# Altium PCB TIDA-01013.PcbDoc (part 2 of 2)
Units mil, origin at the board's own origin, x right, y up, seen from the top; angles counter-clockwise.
Board outline 2500 x 2300 mil, 4 copper layers (Top Layer, Layer 2 -GND, Layer 3 - PWR, Bottom Layer), stack 59.034 mil thick; 218 components, 101 nets, 532 pads, 275 vias.
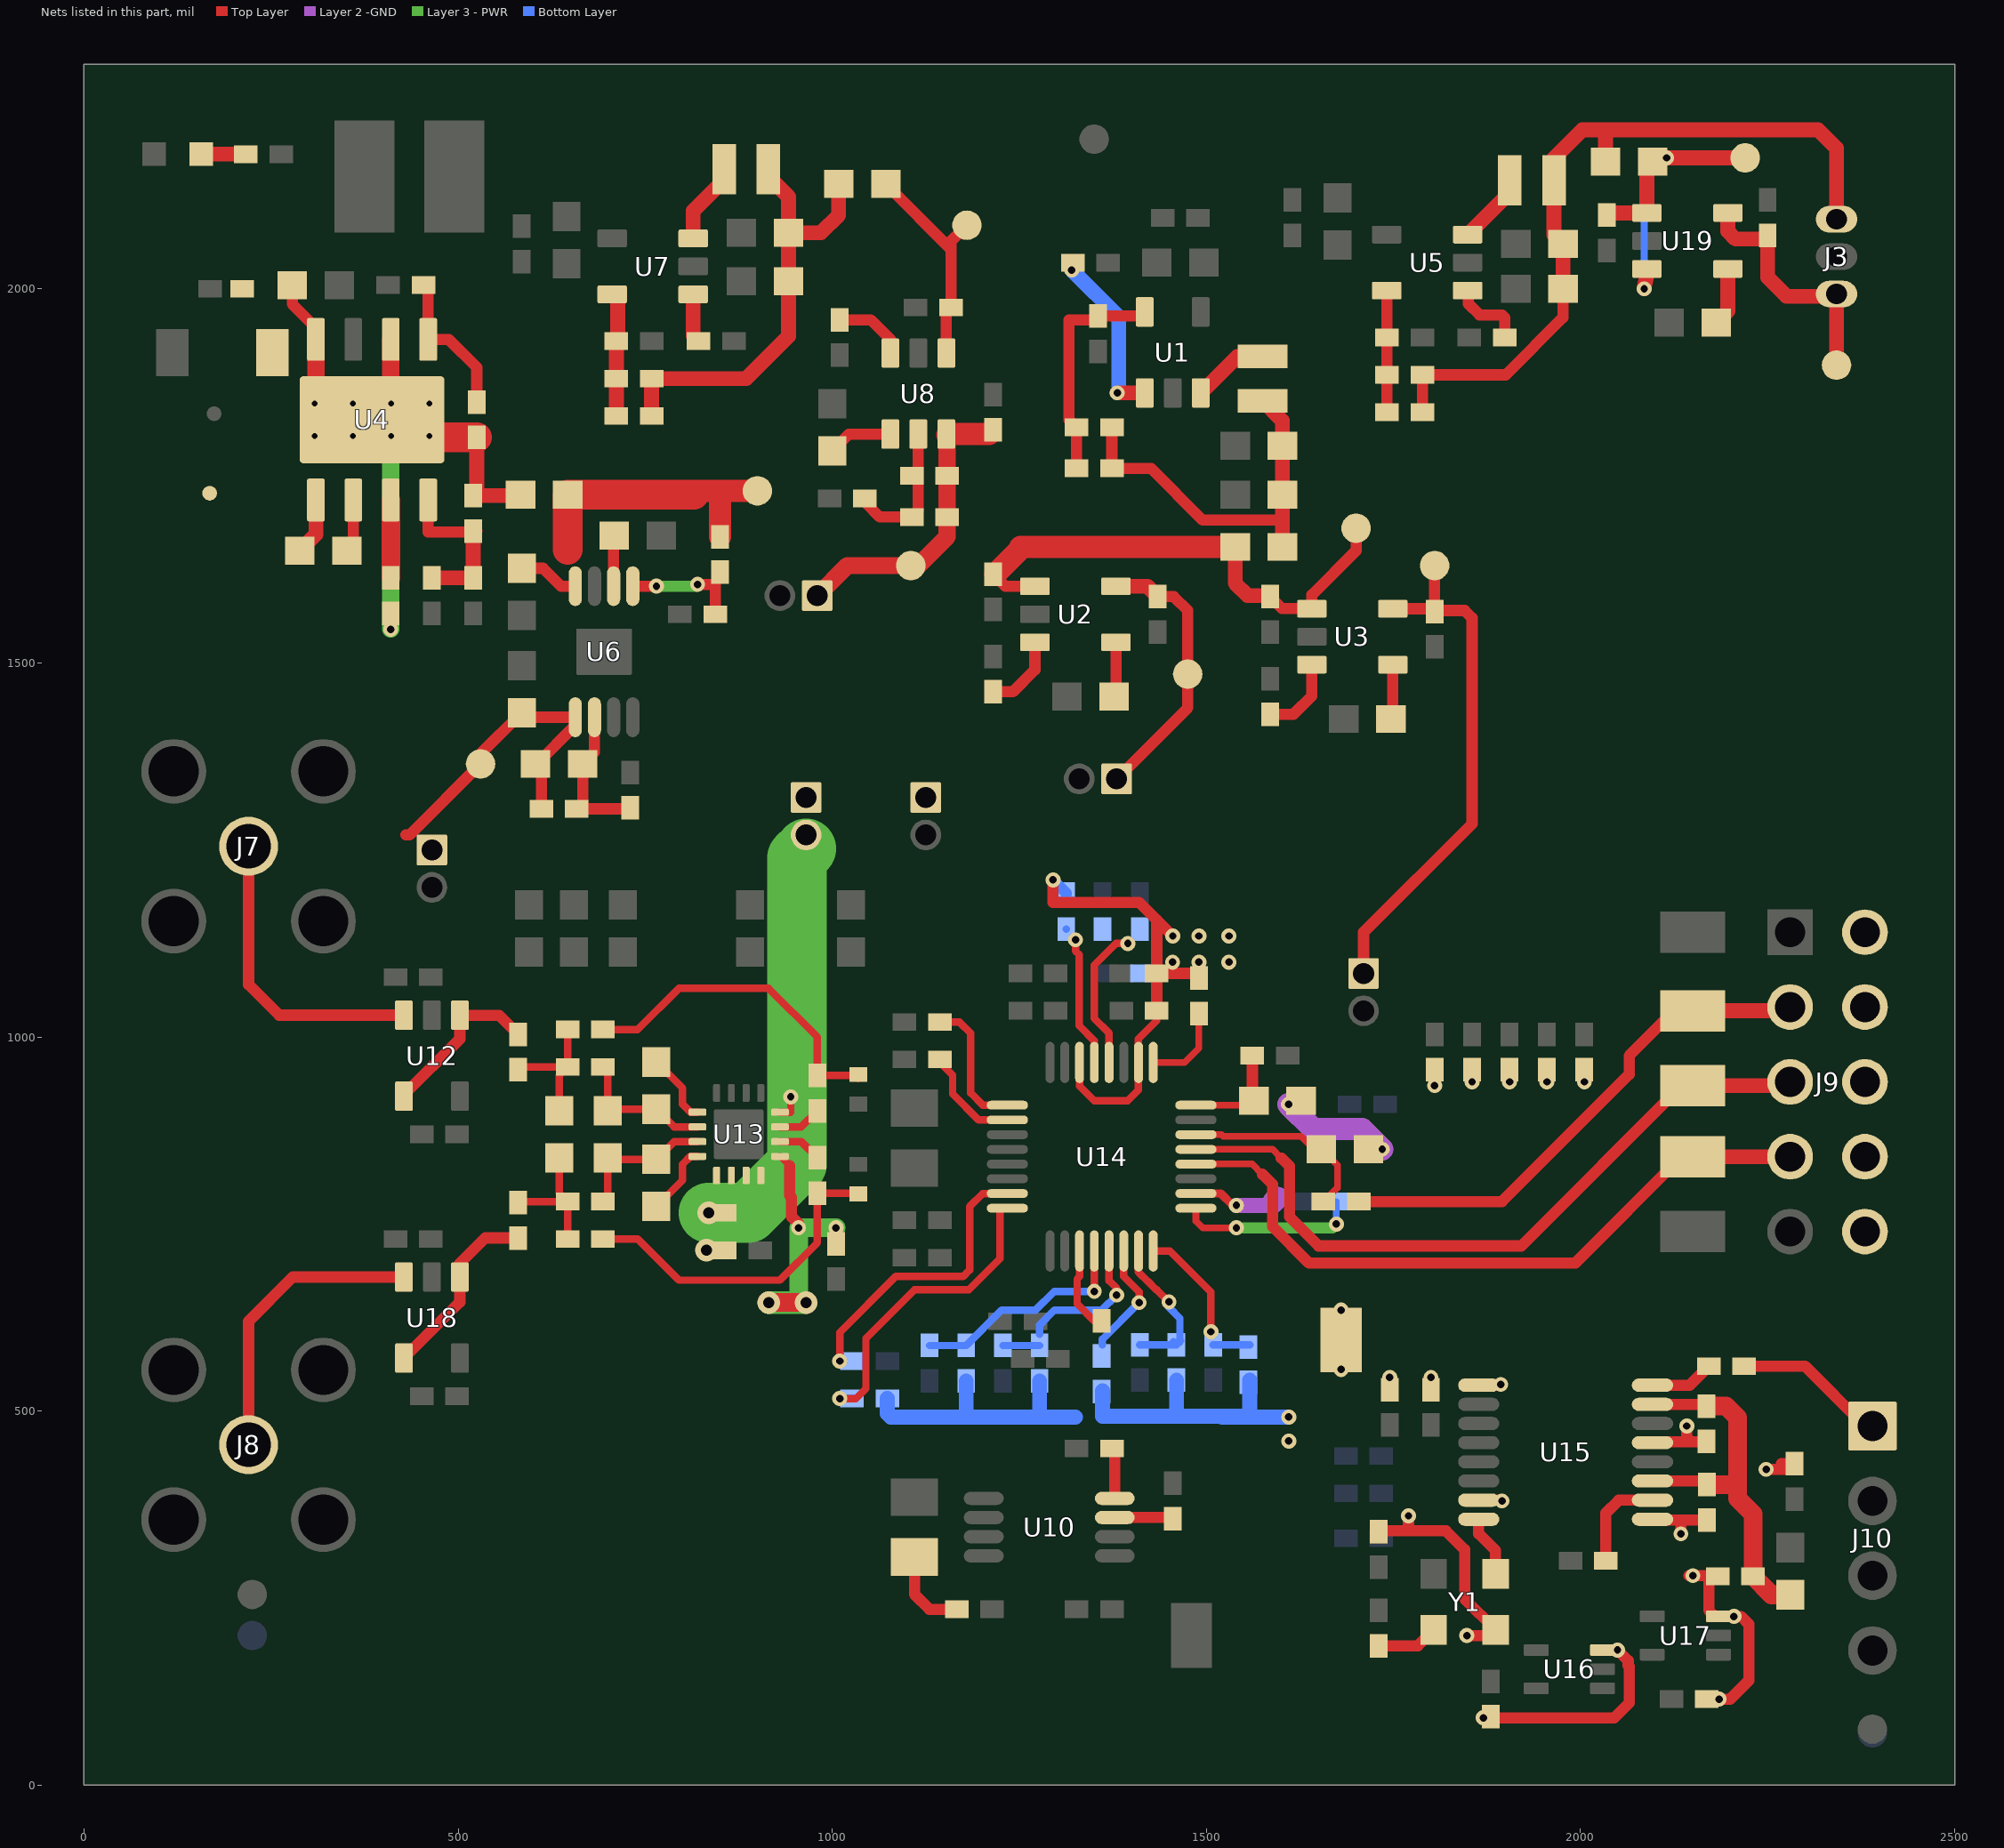
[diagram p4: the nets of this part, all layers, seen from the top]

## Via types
v1: diameter 20, hole 10, Top Layer to Bottom Layer, tented top, 130 vias
v2: diameter 20, hole 10, Top Layer to Bottom Layer, 85 vias
v3: diameter 20, hole 10, Top Layer to Bottom Layer, tented both sides, 20 vias
v4: diameter 19.68, hole 7.87, Top Layer to Bottom Layer, 14 vias
v5: diameter 20, hole 10, Top Layer to Bottom Layer, tented bottom, 12 vias
v6: diameter 30, hole 15, Top Layer to Bottom Layer, tented top, 8 vias
v7: diameter 19.68, hole 7.87, Top Layer to Bottom Layer, tented both sides, 4 vias
v8: diameter 30, hole 15, Top Layer to Bottom Layer, 1 vias
v9: diameter 30, hole 15, Top Layer to Bottom Layer, tented both sides, 1 vias

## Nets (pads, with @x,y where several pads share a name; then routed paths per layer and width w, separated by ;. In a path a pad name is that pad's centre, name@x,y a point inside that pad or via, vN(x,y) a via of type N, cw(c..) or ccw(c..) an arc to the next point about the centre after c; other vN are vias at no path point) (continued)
DGND: C67.1 C68.2 C69.2 C71.2 C72.2 C77.2 C78.1 C79.2 C80.2 C81.1 C82.1 C83.2 C84.2 C85.1 J9.2 J9.4 J9.6 J9.8 J9.10 R42.1 R51.1 R52.2 R54.1 R56.1 R59.1 R60.2 R61.1 R64.1 R71.1 R72.1 R73.1 R74.1 TP18.1 U14.18 U14.26 U14.30 U15.1 U15.7 U15.9 U15.13 U16.3 U17.3 Y1.2 | length 2894.9
  Top Layer w10: U14.30@1330.47,965.98 1330.47,934.53 1350,915 1395,915 1409.21,929.21 U14.26@1409.21,965.98 1409.21,997.56 1433.62,1021.97 ; C67.1@1433.62,1023.62 C67.1@1433.62,1035
  Top Layer w11: U14.18@1485.98,790.79 1519.21,790.79 v2@1535,775
  Top Layer w15: v5(1295,1210) 1295,1180 1410,1180 1433.62,1156.38 ; C67.1@1433.62,1035 C68.2@1433.62,1085 ; v5(1455,1135) 1433.62,1156.38 ; C69.2@1490,1078.62 1483.62,1085 C68.2@1433.62,1085 ; C85.1@1730,338.62 1731.38,340 1820,340 1845,315 1845,248.94 Y1.2@1886.34,207.6 1878.74,200 v2(1848,200) ; 1770,341 v3(1770,360) ; U15.7@1863.86,381.02 1893.98,381.02 v2(1895,380) ; U15.1@1863.86,534.57 1892.4,534.57 v1(1893.39,535.55) ; v1(1870,90) 2045,90 2065,110 2065,158.53 2063.6,159.92 2063.6,166.4 v1(2049.41,180.59) U16.3@2029.29,180.59 ; U15.9@2096.14,355.43 2097.2,354.38 2134,354.38 ; U15.13@2096.14,457.8 2097.5,459.15 2147.5,459.15 ; v1(2134,336) 2134,354.38 ; v1(2142,480) 2142,464.65 2147.5,459.15 ; v1@2145,280 v1(2150,280) 2171.38,280 2171.38,233.62 2179.41,225.59 U17.3@2184.29,225.59 2214.41,225.59 2225,215 2225,140 2200,115 C84.2@2168.62,115 ; C81.1@2168,459.38 2168,459.15 2147.5,459.15 ; C82.1@2169,354.38 2134,354.38 ; v1(2248,422) 2278.38,422 C79.2@2286,429.62 2268.38,429.62 ; C68.2@1433.62,1085 1433.62,1156.38
  Layer 2 -GND w20: v2(1540,775) 1585,775 1590,780
  Layer 2 -GND w30: 1590,780 1595,785 ; v1(1609.7,910) 1642.57,877.13 1707.87,877.13 v1(1735,850)
  Bottom Layer w10: R64.1@1176,537.38 R64.1@1179,540.38 ; R59.1@1276,539.38 R59.1@1277,540.38
  Bottom Layer w15: v5(1295,1210) 1312.78,1192.22 R54.1@1312.78,1191.28
  Bottom Layer w20: R60.2@1073.62,516.79 1073.62,496.52 1078.01,492.13 1325,492.13 ; 1179,496.13 R64.1@1179,540.38 ; 1277,495.13 R59.1@1277,540.38 ; R52.2@1361,527.38 1361,493.13 1557.13,493.13 1558,494 R51.1@1558,541.38 ; 1460,494.13 R56.1@1460,541.38 ; 1521.13,492.13 v2@1607.87,492.13
  other v1: 2185,115 2205,225.59 1745,545 1800,545 1805,935 1855,940 1905,940 1955,940 2005,940 1490,1100 1530,1100
  other v2: 1610,460 1610,492.13 1680,555.63 1680,635 1490,1135 1530,1135
  other v3: 1454.7,1100.04
FILTER0: R58.1 R59.2 U14.13 | length 244.2
  Top Layer w10: U14.13@1369.84,714.02 1369.84,674.3 1380,664.15 v3(1380,655)
  Bottom Layer w10: R58.1@1228,587.62 R59.2@1277,587.62 ; R59.2@1277,602.62 1277,615 1297,635 1360,635 v3(1380,655)
FILTER1: R63.1 R64.2 U14.12 | length 304.2
  Top Layer w10: v3(1350.16,660) U14.12@1350.16,714.02
  Bottom Layer w10: R63.1@1130,587.62 R64.2@1179,587.62 1226.38,635 1271.72,635 1296.72,660 v3(1350.16,660)
FSMODE: R52.1 U14.14 | length 154.2
  Top Layer w10: U14.14@1389.53,714.02 1389.53,679.9 1410,659.42 v1(1410,645)
  Bottom Layer w10: R52.1@1361,588.62 1361,596 v1(1410,645)
MISO: J9.7 TP15.1 U14.20 | length 940.7
  Top Layer w9: U14.20@1485.98,830.16 1561.22,830.16 1575,816.38
  Top Layer w15: 1575,816.38 1588.25,803.13 1588.25,746.75 1637.13,697.87 1992.87,697.87 2135,840 TP15.1@2150,840
  Top Layer w20: TP15.1@2150,840 J9.7@2280,840
MOSI: J9.5 TP14.1 U14.21 | length 970.9
  Top Layer w9: U14.21@1485.98,849.84 1588.41,849.84 1600,838.25
  Top Layer w15: 1600,838.25 1611.12,827.13 1611.12,759.5 1649.87,720.75 1920.75,720.75 2135,935 TP14.1@2150,935 TP14.1@2170,935
  Top Layer w20: TP14.1@2170,935 J9.5@2275,935
NetC3_1: C3.1 C4.1 C5.1 L1.2 R1.1 R2.2 | length 520.8
  Top Layer w15: R2.2@1373.62,1815 C5.1@1373.62,1760 1425.93,1760 1495,1690.93 1594.69,1690.93 1601.5,1697.73
  Top Layer w20: L1.2@1575,1850.47 1601.5,1823.98 C4.1@1601.5,1790 C3.1@1601.5,1725 1601.5,1697.73 R1.1@1601.5,1655
NetC5_2: C5.2 R2.1 R5.2 U1.5 | length 308.3
  Top Layer w15: C5.2@1326.38,1760 R2.1@1326.38,1815 1316.38,1825 1316.38,1958.62 1350,1958.62 R5.2@1355,1963.62 1412.09,1963.62 U1.5@1417.6,1969.13
NetC6_1: C6.1 C9.1 R1.2 TP1.1 U2.1 U3.1 | length 697.1
  Top Layer w15: C6.1@1215,1618.62 1231.12,1602.5 1233.28,1602.5 1233.28,1602.4 U2.1@1270.87,1602.4 ; C9.1@1585,1588.62 1601.12,1572.5 U3.1@1640.87,1572.5 ; U3.1@1640.87,1572.4 U3.1@1640.87,1572.5 ; TP1.1@1700,1680 1700,1650 1640.87,1590.87 U3.1@1640.87,1572.5
  Top Layer w20: R1.2@1538.5,1655 1538.5,1606.5 1555,1590 1583.62,1590 C9.1@1585,1588.62
  Top Layer w30: C6.1@1217.87,1618.62 1251.38,1652.13 1251.38,1655 R1.2@1538.5,1655
NetC7_1: C7.1 J1.1 J11.1 J12.1 TP2.1 U2.5 | length 373.6
  Top Layer w15: J1.1@1380,1345 1475,1440 TP2.1@1475,1485 1475,1570 1456.38,1588.62 C7.1@1435,1588.62
  Top Layer w20: U2.5@1379.13,1602.4 1421.22,1602.4 C7.1@1435,1588.62
NetC8_1: C8.1 U2.4 | length 70
  Top Layer w15: C8.1@1379.13,1457.64 U2.4@1379.13,1527.6
NetC10_1: C10.1 J2.1 TP5.1 U3.5 | length 708.6
  Top Layer w15: J2.1@1710,1085 1710,1140 1855,1285 1855,1560 1845,1570 1806.38,1570 C10.1@1805,1568.62 ; U3.5@1749.13,1572.4 1801.22,1572.4 C10.1@1805,1568.62 ; TP5.1@1805,1630 C10.1@1805,1568.62
NetC11_1: C11.1 U3.4 | length 75.1
  Top Layer w15: C11.1@1746.36,1423.64 1749.13,1426.42 U3.4@1749.13,1497.6
NetC12_1: C12.1 U4.2 | length 59.2
  Top Layer w15: C12.1@360,1658.5 U4.2@360,1717.72
NetC12_2: C12.2 L3.1 U4.1 | length 76.6
  Top Layer w20: C12.2@288.5,1650 310,1671.5 U4.1@310,1717.72
NetC13_2: C13.2 C19.2 C21.2 D2.2 R10.1 R11.1 R13.1 U4.6 U4.8 U4.9@385,1825 | length 717.7
  Top Layer w15: C13.2@278.5,2005 278.5,1979.61 310,1948.11 U4.8@310,1932.28 ; v7(308.23,1846.65) U4.9@310,1848.43 ; U4.9@410,1847.24 v4(410.59,1846.65)
  Top Layer w20: R11.1@520,1723.62 R11.1@525,1723.62 ; R10.1@525,1801.38 R11.1@525,1723.62 ; R13.1@582.13,1723.62 R11.1@525,1723.62
  Top Layer w23: U4.9@310,1848.43 U4.8@310,1932.28 ; U4.9@410,1847.24 U4.6@410,1932.28
  Top Layer w40: U4.9@463.74,1801.38 R10.1@525,1801.38
  Layer 3 - PWR w20: v4@410,1802.76 v4(410.59,1803.35)
  Layer 3 - PWR w23: v1(410,1545) v4@410,1802.76
  other v4: 359.41,1803.35 359.41,1846.65
  other v7: 308.23,1803.35 461.77,1803.35 461.77,1846.65
NetC16_1: C16.1 C17.1 C20.1 J3.3 L2.2 R9.2 R76.1 | length 1028.5
  Top Layer w15: C20.1@1788.62,1835 R9.2@1788.62,1885 1900,1885 1976.5,1961.5 C17.1@1976.5,2000
  Top Layer w20: C17.1@1976.5,2000 C16.1@1976.5,2060 1964.53,2071.97 L2.2@1964.53,2145 1964.53,2174.53 2002.56,2212.56 2317.44,2212.56 2342,2188 J3.3@2342,2093 ; R76.1@2033.5,2170 2033.5,2212.56
NetC18_2: C18.2 R8.1 R11.2 U4.4 | length 216
  Top Layer w15: U4.4@460,1717.72 460,1675 523.62,1675 R11.2@525,1676.38
  Top Layer w20: C18.2@465,1613.62 R8.1@515,1613.62 ; R8.1@520,1613.62 R11.2@520,1671.38
NetC20_2: C20.2 R9.1 R14.2 U5.5 | length 159.8
  Top Layer w15: U5.5@1736.89,1993.62 U5.5@1740.87,1997.6 ; C20.2@1741.38,1835 R14.2@1741.38,1935 U5.5@1741.38,1989.13
NetC21_1: C21.1 U4.3 | length 104.1
  Top Layer w25: C21.1@410,1613.62 U4.3@410,1717.72
NetC22_1: C22.1 R13.2 R15.1 TP7.1 U6.8 | length 481.2
  Top Layer w15: C22.1@585,1626.5 613.5,1626.5 637.4,1602.6 U6.8@656.61,1602.6
  Top Layer w20: C22.1@578.5,1620 C22.1@585,1626.5
  Top Layer w30: 815,1725 820,1730 850,1730 ; R15.1@850,1668.62 850,1730 ; TP7.1@900,1730 850,1730
  Top Layer w40: 646.5,1651.5 R13.2@646.5,1725 815,1725
NetC23_1: C23.1 C24.1 J4.1 R16.2 TP9.1 U6.1 | length 453.3
  Top Layer w15: 430,1270 435,1270 TP9.1@530,1365 530,1378.5 C24.1@585,1433.5 591.1,1427.4 U6.1@656.61,1427.4 656.61,1416.61 605,1365 C23.1@603.5,1365 611.38,1357.13 R16.2@611.38,1305
NetC23_2: C23.2 R16.1 R18.2 U6.2 | length 170.2
  Top Layer w15: R16.1@658.62,1305 R18.2@730,1305 ; R16.1@666.5,1312.87 C23.2@666.5,1365 ; C23.2@682.2,1380.71 U6.2@682.2,1427.4
NetC25_1: C25.1 U6.6 | length 67.7
  Top Layer w15: U6.6@707.8,1602.6 707.8,1669.29 C25.1@708.5,1670
NetC28_1: C28.1 C29.1 C33.1 L4.2 R19.1 R22.2 | length 605.9
  Top Layer w20: C33.1@758.62,1830 R22.2@758.62,1880 885,1880 941.5,1936.5 C28.1@941.5,2010 C29.1@941.5,2075 ; L4.2@909.76,2154.76 941.5,2123.03 C29.1@941.5,2075 ; R19.1@1008.5,2140 1008.5,2098.5 985,2075 C29.1@941.5,2075
NetC30_1: C30.1 C32.1 J5.1 R20.2 TP11.1 U8.6 | length 398.6
  Top Layer w15: TP11.1@1105,1630 TP11.1@1115,1630
  Top Layer w23: J5.1@980,1590 1020,1630 TP11.1@1105,1630 ; TP11.1@1115,1630 1153.62,1668.62 C30.1@1153.62,1695 U8.6@1153.62,1804.65
  Top Layer w30: U8.6@1153.62,1804.65 1154.84,1805.87 C32.1@1209.49,1805.87
NetC30_2: C30.2 R20.1 R25.2 U8.5 | length 185.5
  Top Layer w15: R25.2@1043.62,1715 1063.62,1695 C30.2@1106.38,1695 1115,1703.62 U8.5@1115,1805.87
NetC31_1: C31.1 R19.2 TP10.1 U8.1 | length 305.5
  Top Layer w15: R19.2@1071.5,2140 1158.62,2052.87 ; U8.1@1152.4,1914.13 1152.4,1968.78 C31.1@1158.62,1975 1158.62,2052.87 ; TP10.1@1180,2085 1158.62,2063.62 1158.62,2052.87
NetC33_2: C33.2 R22.1 R27.2 U7.5 | length 166.4
  Top Layer w20: U7.5@705.87,1992.6 713.27,1985.2 713.27,1931.89 R27.2@711.38,1930 R22.1@711.38,1880 C33.2@711.38,1830
NetC34_1: C34.1 U8.4 | length 86.9
  Top Layer w15: C34.1@1000,1783.5 1022.36,1805.87 U8.4@1077.6,1805.87
NetC47_2: C47.2 R32.2 | length 114.7
  Top Layer w15: C47.2@1110,305 1110,255 1130,235 R32.2@1166.38,235
NetC50_1: C50.1 U10.4 | length 62.6
  Top Layer w15: U10.4@1377.6,383.39 C50.1@1377.6,446.02
NetC51_1: C51.1 U13.9 | length 345.9
  Top Layer w9: U13.9@930.12,840.47 930.35,840.47 942.91,827.91
  Top Layer w15: 942.91,827.91 942.91,788.18 945.41,785.68 945.41,760 955,750.41 v1(955,745)
  Top Layer w25: v6(915,645) v6(965,645)
  Layer 3 - PWR w25: v6@955,655 v1(955,745) v1(1005,745)
  Layer 3 - PWR w30: v6(915,645) v6(965,645)
NetC52_1: C52.1 U13.1 | length 95.2
  Top Layer w10: C52.1@765,966.5 800,931.5 800,910 810.47,899.53 U13.1@819.88,899.53
NetC52_2: C52.2 C54.1 R37.2 U13.2 | length 182.6
  Top Layer w10: R37.2@700,953.62 C54.1@700,901.5 702.01,903.5 C52.2@765,903.5 788.66,879.84 U13.2@819.88,879.84
NetC53_1: C53.1 R35.1 R36.2 R37.1 | length 176
  Top Layer w10: R36.2@583.62,960 R37.1@646.38,960 ; C53.1@635,901.5 635,948.62 R37.1@646.38,960 ; R35.1@646.38,1010 R37.1@646.38,960
NetC53_2: C53.2 R40.2 R41.1 R45.1 | length 180.2
  Top Layer w10: R40.2@580,778.62 581.38,780 R41.1@646.38,780 ; C53.2@635,838.5 635,791.38 R41.1@646.38,780 ; R45.1@646.38,730 R41.1@646.38,780
NetC54_2: C54.2 C62.2 R41.2 U13.3 | length 182.6
  Top Layer w10: R41.2@700,786.38 C54.2@700,838.5 702.01,836.5 C62.2@765,836.5 788.66,860.16 U13.3@819.88,860.16
NetC57_1: C57.1 U19.4 | length 77.9
  Top Layer w20: C57.1@2181.5,1955 2196.82,1970.32 U19.4@2196.82,2026.6
NetC62_1: C62.1 U13.4 | length 95.2
  Top Layer w10: C62.1@765,773.5 800,808.5 800,830 810.47,840.47 U13.4@819.88,840.47
NetC69_1: C69.1 U14.25 | length 115.4
  Top Layer w9: U14.25@1428.9,965.98 1470.98,965.98 1490,985 C69.1@1490,1031.38
NetC70_2: C70.2 U14.1 | length 198.3
  Top Layer w10: C70.2@1143.62,1020 1170,1020 1185,1005 1185,925 1201.1,908.9 U14.1@1234.02,908.9 U14.1@1249.02,908.9
NetC71_1: C71.1 R47.1 U14.24 | length 163.9
  Top Layer w9: U14.24@1485.98,908.9 1557.4,908.9 C71.1@1577.4,908.9 ; R47.1@1561.38,975 R47.1@1563.5,972.87
  Top Layer w10: C71.1@1557.4,908.9 C71.1@1563.5,915
  Top Layer w15: R47.1@1561.38,975 1561.38,917.13 C71.1@1563.5,915
NetC72_1: C72.1 R48.1 U14.22 | length 270.4
  Top Layer w9: U14.22@1485.98,869.53 1520,869.53 1522.48,867.05 1626.45,867.05 C72.1@1656.38,837.13 ; C72.1@1653.5,850 1675,828.5 1675,798.62 R48.1@1656.38,780
NetC73_1: C73.1 U14.2 | length 152.2
  Top Layer w10: C73.1@1143.62,966.38 1160.83,949.17 1160.83,923.87 1195.49,889.21 U14.2@1234.02,889.21 U14.2@1249.02,889.21
NetC74_1: C74.1 U14.11 | length 104.1
  Top Layer w10: U14.11@1330.47,714.02 1330.47,679.9 1327.28,676.71 1327.28,643.34 C74.1@1350,620.62
NetC89_1: C89.1 R76.2 TP6.1 U19.1 U19.3 | length 466.9
  Top Layer w20: C89.1@2035,2098.62 2037.78,2101.4 U19.1@2088.55,2101.4 R76.2@2088.55,2167.06 ; v1(2085,2000) 2088.55,2017.17 U19.3@2088.55,2026.6 ; R76.2@2096.5,2175 TP6.1@2220,2175 TP6.1@2225,2180
  Bottom Layer w10: v1(2085,2000) 2085,2150 v1(2115,2175)
NetC90_1: C90.1 J3.1 TP17.1 U19.5 | length 344.6
  Top Layer w20: U19.5@2196.82,2101.4 2196.82,2076.82 2207.09,2066.55 2245.17,2066.55 C90.1@2250,2071.38 2250,2015 2275,1990 2339,1990 J3.1@2342,1993 TP17.1@2342,1898 TP17.1@2346,1894
NetD1_2: D1.2 R75.1 | length 59.9
  Top Layer w20: D1.2@156.5,2180 R75.1@216.38,2180
NetJ7_1: J7.1 U12.3 | length 409.5
  Top Layer w15: J7.1@220,1255 220,1070 260.87,1029.13 U12.3@427.6,1029.13
NetJ8_1: J8.1 U18.3 | length 397.1
  Top Layer w15: J8.1@220,455 220,620 279.13,679.13 U18.3@427.6,679.13
NetL1_1: L1.1 U1.3 | length 102.8
  Top Layer w20: U1.3@1492.4,1860.87 1541.06,1909.53 L1.1@1575,1909.53
NetL2_1: L2.1 U5.3 | length 95.9
  Top Layer w20: U5.3@1849.13,2072.4 1905.47,2128.74 L2.1@1905.47,2145
NetL4_1: L4.1 U7.3 | length 109.7
  Top Layer w20: U7.3@814.13,2067.4 814.13,2104.13 855.47,2145.47 L4.1@855.47,2160
NetR3_1: R3.1 U2.3 | length 104.8
  Top Layer w15: R3.1@1215,1461.38 1241.38,1461.38 1270.87,1490.87 U2.3@1270.87,1527.6
NetR4_1: R4.1 U1.1 | length 227.7
  Top Layer w20: v1(1380.87,1860.87) U1.1@1417.6,1860.87
  Bottom Layer w20: v1(1320,2025) 1382.87,1962.13 1382.87,1862.87 v1(1380.87,1860.87)
NetR6_1: R6.1 U3.3 | length 107.7
  Top Layer w15: R6.1@1585,1431.38 1616.38,1431.38 1640.87,1455.87 U3.3@1640.87,1497.6
NetR7_2: R7.2 R10.2 U4.5 | length 193.2
  Top Layer w15: R7.2@460,1998.62 U4.5@460,1932.28 487.72,1932.28 525,1895 R10.2@525,1848.62
NetR12_1: R12.1 U5.1 | length 100.7
  Top Layer w15: U5.1@1849.13,1997.6 1850,1996.73 1850,1980 1865,1965 1895,1965 1898.62,1961.38 R12.1@1898.62,1935
NetR15_2: R15.2 R17.2 U6.5 | length 151.2
  Top Layer w15: U6.5@733.39,1602.6 v1(765,1602.6) ; v1(820,1605) 843.62,1605 R17.2@843.62,1565
  Layer 3 - PWR w15: v1(765,1602.6) 817.6,1602.6 v1(820,1605)
NetR23_1: R23.1 U8.3 | length 96.7
  Top Layer w15: R23.1@1010,1958.62 1051.38,1958.62 1077.6,1932.4 U8.3@1077.6,1914.13
NetR26_1: R26.1 U7.1 | length 65.6
  Top Layer w20: U7.1@814.13,1992.6 814.13,1937.24 R26.1@821.38,1930
NetR34_2: R34.2 U10.3 | length 76
  Top Layer w15: U10.3@1377.6,357.8 R34.2@1453.58,357.8
NetR35_2: R35.2 R38.1 R39.2 | length 444.1
  Top Layer w10: R35.2@693.62,1010 740,1010 795,1065 915,1065 980,1000 R39.2@980,948.62 1031.06,948.62 R38.1@1035,944.68
NetR36_1: R36.1 U12.1 U12.4 | length 227.4
  Top Layer w15: U12.4@427.6,920.87 427.6,922.6 502.4,997.4 U12.1@502.4,1029.13 502.54,1029 554.62,1029 R36.1@580,1003.62
NetR39_1: R39.1 U13.11 | length 58.8
  Top Layer w10: U13.11@930.12,879.84 958.46,879.84 R39.1@980,901.38
NetR40_1: R40.1 U18.1 U18.4 | length 249.2
  Top Layer w15: U18.4@427.6,570.87 502.4,645.67 U18.1@502.4,679.13 502.4,697.4 536.38,731.38 R40.1@580,731.38
NetR43_1: R43.1 R44.2 R45.2 | length 452.9
  Top Layer w10: R45.2@693.62,730 740,730 795,675 930,675 980,725 R44.2@980,791.38 1031.06,791.38 R43.1@1035,795.32
NetR44_1: R44.1 U13.10 | length 58.8
  Top Layer w10: U13.10@930.12,860.16 958.46,860.16 R44.1@980,838.62
NetR49_2: R49.2 U14.7 | length 403.8
  Top Layer w10: v3(1010,566.79) 1010,605 1085,680 1175,680 1183.58,688.58 1183.58,773.29 1201.08,790.79 U14.7@1234.02,790.79 U14.7@1249.02,790.79
NetR54_2: R54.2 R55.1 U14.29 | length 174.4
  Top Layer w10: v5(1325,1130) 1325,1115 1330,1110 1330,1015 1350.16,994.84 U14.29@1350.16,965.98
NetR57_1: R57.1 U14.28 | length 195.2
  Top Layer w10: U14.28@1369.84,965.98 1369.84,1005.16 1350,1025 1350,1095.87 1379.13,1125 v5(1395,1125)
NetR60_1: R60.1 U14.8 | length 398
  Top Layer w10: v3(1010,516.79) 1031.79,516.79 1045,530 1045,597.35 1109.78,662.13 1182.4,662.13 1224.02,703.74 ; 1224.02,704.02 U14.8@1224.02,771.1
NetR62_1: R62.1 U14.17 | length 229.2
  Top Layer w9: U14.17@1485.98,771.1 1485.98,754.02 1495,745 v2@1530,745
  Layer 3 - PWR w15: v2(1540,745) 1668.62,745 v3(1673.62,750)
  Bottom Layer w9: v3@1673.62,751.38 R62.1@1673.62,780
NetR65_1: R65.1 U15.16 | length 85.8
  Top Layer w15: U15.16@2096.14,534.57 2145.94,534.57 R65.1@2171.38,560
NetR66_1: R66.1 U15.10 | length 133.3
  Top Layer w15: R66.1@2033.62,300 2033.62,363.62 2051.02,381.02 U15.10@2096.14,381.02
NetR67_1: R67.1 Y1.1 | length 82.5
  Top Layer w15: R67.1@1730,186.38 1782.44,186.38 Y1.1@1803.66,207.6
NetU15_8: U15.8 Y1.3 | length 82.3
  Top Layer w15: U15.8@1863.86,355.43 1863.86,336.14 1886.34,313.66 Y1.3@1886.34,282.4
OSR0: R50.1 R51.2 U14.16 | length 201.9
  Top Layer w10: U14.16@1428.9,714.02 1450.98,714.02 1506,659 v5(1506,606)
  Bottom Layer w10: R50.1@1509,588.62 R51.2@1558,588.62
OSR1: R53.1 R56.2 U14.15 | length 208
  Top Layer w10: U14.15@1409.21,714.02 1409.21,685.79 1410.12,684.88 1410.12,684.58 1421.12,673.58 1421.42,673.58 1432.87,662.13 1433.87,662.13 v3(1450,646)
  Bottom Layer w10: R53.1@1411,588.62 R56.2@1460,588.62 ; v3(1450,646) 1450,638.5 1464.5,624 R56.2@1464.5,592.12 ; R56.2@1456,592.62 R56.2@1460,588.62 ; R56.2@1465.5,594.12 R56.2@1460,588.62
SCLK: J9.3 R48.2 TP13.1 | length 696.6
  Top Layer w15: R48.2@1698.62,780 1895,780 2065,950 2065,975 2125,1035 TP13.1@2150,1035
  Top Layer w20: TP13.1@2150,1035 J9.3@2275,1035
THS_3.3V: C59.1 C60.2 J11.2 U13.5 U13.6 U13.7 U13.8 U13.12 | length 606.5
  Top Layer w10: U13.12@930.12,899.53 944.53,899.53 v1(944.53,920)
  Layer 3 - PWR w80: v6(835,765) 888.11,765 952.87,829.76 952.87,1239.5 J11.2@965,1251.63
  other v9: 832,715
TIVA_16MHZ: J10.1 R65.2 | length 194.5
  Top Layer w15: R65.2@2218.62,560 2300,560 J10.1@2380,480
VDDO: C80.1 C81.2 C82.2 L7.2 U15.11 U15.15 | length 514.9
  Top Layer w15: U15.11@2096.14,406.61 C82.2@2169.76,406.61 ; U15.15@2096.14,508.98 C81.2@2168,508.98
  Top Layer w25: C81.2@2168,506.62 2194.38,506.62 2209.63,491.37 2209.63,401 ; C82.2@2169,401.62 2208.25,401.62 2208.87,401 2209.63,401 ; L7.2@2280,254.5 2255.12,254.5 C80.1@2230.62,279 2230.62,362.38 2209.63,383.37 2209.63,401
pads on no net: FID1.1 FID2.1 FID3.1 FID4.1 FID5.1 FID6.1 H1.0 H2.0 J10.4 LBL1.0 U4.9@385,1825 U6.3 U6.7 U13.17@875,870 U15.2 U15.4 U15.5 U15.6 U15.12 U15.14
copper on no net:
  other v1: 1690,1860

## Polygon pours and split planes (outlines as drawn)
DGND on Layer 2 -GND "LAYER_2_-GND_DGND_P012" (solid, remove dead copper, pour order 12): 1600,310 1785,310 1785,0 2500,0 2500,1120 2500,1190 2430,1190 2425,1185 2330,1185 2330,965 1765,965 1765,1145 1910,1145 1910,1395 1280,1395 1280,1169 1415,1169 1415,1025 1665,1025 1665,920 1590,920 1590,830.16 1515,830.16 1515,760 1600,760
AGND on Layer 2 -GND "LAYER_2_-GND_AGND_P014" (solid, remove dead copper, pour order 14): 0,2300 2500,2300 2500,0 0,0
AGND on Top Layer "TOP_LAYER_AGND_P036" (solid, remove dead copper, pour order 36): 0,2300 2500,2300 2500,1218.53 2301.47,1218.53 2301.47,1006.47 2290,995 2278.53,1006.47 1805.34,1006.47 1805.34,1104.49 1950,1104.49 1950,1439.94 1239.65,1439.94 1239.65,1170 430,1170 430,1445 0,1445
NetC13_2 on Top Layer "TOP_LAYER_NETC13_2_P008" (solid, remove dead copper, pour order 8): 225,1870 317.32,1870 317.32,1962.32 320,1965 300,1985 300,2000 300,2020 295,2025 225,2025 225,1962.32 210,1890
AGND on Top Layer "REFN" (solid, pour order 16): 1286,636 1276,626 1276,615 1276,557 1281,552 1313,552 1314,553 1326,553 1333,560 1335,562 1335,590 1335,611 1322,624 1309.5,636.5 1304,636.5 1286.5,636.5 1286,636
5.2V on Layer 3 - PWR "LAYER_3_-_PWR_5.2V_P024" (solid, remove dead copper, pour order 24): 950,1620 843.28,1620 834.13,1610.85 510,1286.72 510,480 610,480 610,1270 880,1540 950,1540
D1.8V on Layer 3 - PWR "LAYER_3_-_PWR_D1.8V_P022" (solid, remove dead copper, pour order 22): 2495,2065 2185,2065 2185,1175 2504.78,1175
3.3V on Layer 3 - PWR "LAYER_3_-_PWR_3.3V_P018" (solid, remove dead copper, pour order 18): 2159,1760 1190,1760 958,1528 958,1442 970,1430 1065,1430 1180,1430 1310,1300 1423,1300 1508,1385 1553,1430 1806,1430 2168.46,1430 2168.46,1750.54
ADC_3.3V on Layer 3 - PWR "LAYER_3_-_PWR_ADC_3.3V_P015" (solid, remove dead copper, pour order 15): 1374.65,1130 1034,1130 1034,539 1559.65,539 1559.65,719.31 1476,719.31 1476,871 1555,871 1555,960 1595.59,960 1595.59,984 1374.65,984
3.3V on Layer 3 - PWR "LAYER_3_-_PWR_3.3V_P026" (solid, remove dead copper, pour order 26): 989.19,1514.19 968.37,1535 890,1535 620,1265 620,325 620,25 1745,25 1745,214.59 1745,270 1559.65,270 1559.65,500 770,500 770,1275 925,1430 990.18,1430
-5.2V on Layer 3 - PWR "LAYER_3_-_PWR_-5.2V_P028" (solid, remove dead copper, pour order 28): 505,1220 410,1220 410,480 505,480
no net on Layer 3 - PWR "LAYER_3_-_PWR_NONET_P032" (solid, remove dead copper, pour order 32): 885,620 1020,620 1020,750 885,750
D3.3V on Layer 3 - PWR "LAYER_3_-_PWR_D3.3V_P038" (solid, remove dead copper, pour order 38): 1680,1057 1680,962 1683,959 1745,897 1745,838 1745,561 1699,515 1680,515 1680,455 1843,455 1896,508 1896,850 1742,1004 1742,1057
D1.8V on Layer 3 - PWR "LAYER_3_-_PWR_D1.8V_P040" (solid, remove dead copper, pour order 40): 2502.51,1185 2502.51,25.49 1785,25.49 1785,309 1598,309 1598,755.5 1602,759.5 1600.69,760.81 1523.09,760.81 1523.09,762.93 1515,771.02 1515.84,771.86 1515.84,822.09 1523.9,830.16 1524.48,830.73 1590,830.73 1590,911.09 1603.9,925 1607,925 1665,925 1666.81,926.81 1665,928.62 1665,1024 1665,1062 1765,1062 1765,981 1784,962 1787,965 2301.47,965 2301.47,1185
D1.8V on Layer 3 - PWR "LAYER_3_-_PWR_D1.8V_P042" (solid, remove dead copper, pour order 42): 2500,1315 2330,1315 2330,210 2500,210

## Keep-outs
Keep-Out Layer:
  text ".Layer_Name" at -133,-1298.49 h60

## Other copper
Top Layer:
  rectangle net AGND: 848.98,2000.12 868.62,2020
  rectangle net 12V_SOURCE: 335,2005 415,2090
  rectangle net NetC13_2: 510,1710 605,1815
  rectangle net NetC22_1: 595,1597.26 662.71,1650
  rectangle net AGND: 485,2020 665,2050
  rectangle net AGND: 660,2015 895,2045
  rectangle net ADC_3.3V: 1235,945 1291.1,995
  rectangle net AGND: 1310,428.35 1344.1,444.14
  region net ADC_3.3V: 1125,770 1170,770 1170,731 1170,694 1125,694
  region net NetC16_1: 1945,2150 2055,2150 2055,2225 1945,2225
  region net AGND: 545,1135 1045,1135 1045,1080 545,1080
  region net AGND: 545,1204.98 1053.53,1204.98 1055,1203.54 1055,1155 545,1155
  region net AGND: 75,2030 160,2030 160,1890 205.49,1844.51 228.87,1844.51 228.87,1799.87 75,1799.7
  region net NetC13_2: 195,2023.19 195,1956 195,1872.38 215.39,1871.68 319,1871.68 319,1956 315,1956 296.81,1974.19 296.81,2023.19
  region net NetL1_1: 1504,1858.52 1503.54,1858.97 1538.57,1894 1609.43,1894 1610,1893.43 1610,1925 1481,1925 1481,1841 1504,1841
  region net NetL2_1: 1827.87,2061 1827.87,2177.87 1923.78,2177.87 1923.78,2110 1921.78,2108 1908,2108 1861,2061
  region net NetC12_2: 320.91,1745.79 243.44,1746.12 225.39,1764.16 91.02,1764.16 91.02,1724.16 185.02,1630.16 323.02,1630.16
  region net AGND: 885,776.81 930.04,776.81 930.04,695.03 885,694.99
  region net THS_3.3V: 910,825 820,825 820,805 805,790 805,694.5 870,694.5 870,780 880,790 910,790
  region net 5.2V: 480,481.03 584.67,481.03 584.67,595 480,595
  region net 5.2V: 480,851.31 583.97,851.31 583.97,925 566.77,925 551.77,940 480,940
  region net -5.2V: 455,665 455,705 440,720 440,790 490,790 490,718.35 475,703.35 475,665
  region net -5.2V: 477,1015 477,1064 493.9,1080.9 493.9,1220 440,1220 440,1075 453,1062 453,1015
  region net 12V_SOURCE: 1515,2180 1515,2060 1593.35,2060 1593.35,2180
  region net 12V_SOURCE: 735,2065.15 735,2165 620,2165 620,2064.93
  region net NetC28_1: 900,2200 900,2113.7 920,2093.7 920,2055 965,2055 965,2200
  region net NetL4_1: 835.12,2105.12 854.57,2124.57 870,2124.57 870,2200 792.87,2200 792.87,2060.2 834.9,2060.2
  region net NetC16_1: 1950,2175 1995,2175 1995,2041.3 1950,2041.3
  region net NetC3_1: 1625,1870 1580,1870 1580,1770 1625,1770
  region net AGND: 440,2120 440,2065 499.98,2005.02 660,2005.02 660,2050 550.71,2050 550.71,2120
  region net NetC31_1: 1140,1892.61 1140,2035 1050,2125 1050,2165 1220,2165 1220,1892.61
  region net AGND: 1235.42,1875.4 1139.88,1875.12 1130,1885 1130,1996.65 1100,1996.65 1100,1875 1029.57,1875 1028.54,1876.02 1030,1877.48 1030,1930 980,1930 935,1885 935,1715 945,1705 1010,1705 1010,1741.65 970.79,1741.65 970.79,1825 1015,1825 1025,1835 1235,1835
  region net NetC30_1: 960,1556.67 1195,1556.67 1195,1645 1230,1680 1230,1825 1140,1825 1140,1680 1115,1655 960,1655
  region net NetC23_1: 410,1230 625,1230 625,1375 662.71,1412.71 662.71,1456.04 571.04,1456.04 410,1456.04
  region net NetC7_1: 1354.88,1585 1435,1585 1456.65,1563.35 1456.65,1471.65 1360,1375 1360,1335 1360,1310 1510,1310 1510,1625 1355.37,1625
  region net NetC7_1: 925,1425 1420,1425 1419.8,1375 1235,1375 1235,1300 925,1300
  region net NetC3_1: 1544.81,1870 1650,1870 1650,1635 1580,1635 1580,1825 1575,1830 1545.31,1830
  region net 12V_SOURCE: 1465.2,1950 1593.35,1950 1593.35,2180.2 1465.2,2180.2
  region net NetC6_1: 1315,1599.8 1315,1655 1235,1655 1215,1635 1215,1599.8
  region net 12V_SOURCE: 344,1901.87 344,1975 325,1975 325,2010 405,2010 405,1975 375,1975 375,1901.87
  region net 12V_SOURCE: 1524.88,2100 1700,2100 1720,2080 1720,2065.2 1760,2065.2 1760,2180 1525.07,2180
  region net NetC10_1: 1730,1555 1840,1555 1840,1480 1780,1420 1780,1320 1675,1194 1675,1065 1770,1065 1770,1129.55 1880,1254.55 1880,1650 1840,1650 1730,1650
  region net DGND: 1415,1145 1400,1160 1280,1160 1280,1190 1280,1224.13 1280,1224.73 1325,1224.73 1325,1190 1495,1190 1545,1140 1545,1055 1455,1055 1455,1005 1415,1005 1415,1055
  region net AGND: 845.18,915 910,915 910,948 906.3,951.7 905.15,950.55 873.86,950.55 873.86,1045 812.99,1045 812.99,922.31
  region net 3V_REF: 1080,360 1140,360 1140,350 1240,350 1240,457 1238,462.65 1079.43,462.65 1079.43,420 1080,420
  region net 3.3V: 1350,340 1420,340 1420,215 1350,215
  text ".Layer_Name" at -133,-1298.49 h60
Layer 2 -GND:
  pour cut-out: 1595,950 1595,1010 1655,1010 1655,950
  pour cut-out: 390,1404 390,1130 1279,1130 1279,1169 430,1169 430,1444 0,1444 0,1404
Layer 3 - PWR:
  rectangle net NetC13_2: 286.57,1769.88 483.43,1880.12
  rectangle net 12V_SOURCE: 560,2060 1593.35,2165
  rectangle net 12V_SOURCE: 340.04,2125 1593.35,2224.96
  region net 5.2V: 950,1620 880,1620 880,1540 950,1540
  region net THS_3.3V: 795.43,782.49 807.94,795 885,795 885,703.19 793.73,703.19
  region net D1.8V: 1334.77,1220 2240,1220 2240,1170 1333.05,1170 1330,1170 1330,1220
Bottom Layer:
  rectangle net DGND: 1590,445 1630,505
  region net DGND: 1395.12,1105 1440,1105 1440,1160 1550,1160 1550,1069.31 1479.31,1069.31 1394.25,1069.31 1394.25,1105
  region net AGND: 1275.02,1110.87 1325,1110.87 1325,1106.65 1385,1106.65 1385,1070 1342,1070 1342,1055.5 1274.93,1055.5
  region net DGND: 1060,525 1060,485 1125,485 1155,455 1630,455 1630,500 1095,500 1095,525
  region net NetR54_2: 1360,1155 1360,1130 1315,1130 1315,1155
  text ".Layer_Name" at -133,-1298.49 h60

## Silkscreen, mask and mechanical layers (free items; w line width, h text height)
Top Overlay:
  text "DNP" at 1200,2020 h30
  text "DNP" at 568,1904 h30 r90
  text "DNP" at 1830,1820 h30
  text "DNP" at 808,1816 h30
  text "DNP" at 1750,1770 h30
  text "DNP" at 695,1760 h30
  text "DNP" at 1410,1699 h30
  text "DNP" at 880,1500 h30
  text "DNP" at 1786.53,1170 h30
  text ".Layer_Name" at -133,-1298.49 h60
Bottom Overlay:
  text "DNP" at -1590,1890 h72.83 r270
  text "DNP" at 1400,1380 h30
  text "DNP" at 1385,790 h30 r270
  text "DNP" at 1490,790 h30 r270
  text "DNP" at 1106,753 h30 r270
  text "DNP" at 1248,746 h30 r270
  text "DNP" at 1530,431 h30
  text "DNP" at 1529,349 h30
  text ".Layer_Name" at -133,-1298.49 h60
Top Paste:
  text ".Layer_Name" at -133,-1298.49 h60
Bottom Paste:
  text ".Layer_Name" at -133,-1298.49 h60
Top Solder:
  text ".Layer_Name" at -133,-1298.49 h60
  text ".Layer_Name" at -133,-1298.49 h60
Bottom Solder:
  text ".Layer_Name" at -133,-1298.49 h60
Drill Guide:
  text ".Layer_Name" at -133,-1298.49 h60
M1 Board Outline:
  the board outline again, w10
  text ".Layer_Name" at -133,-1298.49 h60
M2 Board Dimensions:
  rectangle: -585,-840 -210,-715
  rectangle: -710,-715 -585,-590
  lines w7: -710,-715 290,-715 ; -710,-590 -710,-840 290,-840 290,-590 ; -585,-840 -585,-590 ; -460,-840 -460,-590 ; -210,-840 -210,-590 ; 40,-840 40,-590
  text ".Layer_Name" at -133,-1298.49 h60
M3 3D STEP Top:
  text ".Layer_Name" at -133,-1298.49 h60
M4 3D STEP Bottom:
  text ".Layer_Name" at -133,-1298.49 h60
M5 Assembly Top:
  lines w10: -1002,-1370.17 5598,-1370.17 ; -1002,-1166.83 5600,-1166.83 ; -1002,-963.5 -1002,-1573.5 3003,-1573.5 5600,-1573.5 5600,-963.5 -1001.5,-963.5 -1001.5,-1573.5 574,-1573.5 ; 1463,-1573.5 1463,-963.5 ; 2730,-1166.83 2730,-963.5 ; 3570,-1166.83 3570,-963.5 ; 4192,-1580 4192,-1377.17
  text "COMPONENTS MARKED 'DNP' SHOULD NOT BE POPULATED." at 443.5,-758.5 h60
  text "ASSEMBLY VARIANT:" at 443,-874 h60
  text ".VariantName" at 1479,-874 h60
  text "PCB VIEWED FROM TOP SIDE" at -938.5,-1095.67 h60
  text "BOARD #:" at 1538,-1095.67 h60
  text ".PRJ_Number" at 2083.5,-1095.67 h60
  text "REV:" at 2928,-1095.67 h60
  text ".PCB_Rev" at 3219.5,-1095.67 h60
  text "SVN REV:" at 3766,-1095.67 h60
  text ".VersionControl_RevNumber" at 4272,-1095.67 h60
  text "TID #:" at 1538,-1299 h60
  text ".TID" at 2083.5,-1299 h60
  text "PLOT NAME =" at -938.5,-1504.34 h60
  text ".plot_File_Name" at -133,-1504.34 h60
  text "GENERATED    :" at 1540,-1504.34 h60
  text ".Print_Date" at 2409.5,-1504.34 h60
  text ".Print_Time" at 3138.5,-1504.34 h60
  text "TEXAS INSTRUMENTS" at 4403,-1504.34 h60
M6 Assembly Bottom:
  lines w10: -1002.5,-1167.33 5599.5,-1167.33 ; -1000.5,-1370.67 5599.5,-1370.67 ; 405.5,-1580.5 405.5,-1377.67 ; 1027.5,-1167.33 1027.5,-964 ; 1867.5,-1167.33 1867.5,-964 ; 3134.5,-1574 3134.5,-964 ; 4023.5,-1574 5599,-1574 5599,-964 -1002.5,-964 -1002.5,-1574 1594.5,-1574 5599.5,-1574 5599.5,-964
  text "COMPONENTS MARKED 'DNP' SHOULD NOT BE POPULATED." at 5392,-758 h60
  text ".VariantName" at 4348,-874 h60
  text "ASSEMBLY VARIANT:" at 5387,-874 h60
  text ".VersionControl_RevNumber" at 325.5,-1096.17 h60
  text "SVN REV:" at 831.5,-1096.17 h60
  text ".PCB_Rev" at 1378,-1096.17 h60
  text "REV:" at 1669.5,-1096.17 h60
  text ".PRJ_Number" at 2514,-1096.17 h60
  text "BOARD #:" at 3059.5,-1096.17 h60
  text "PCB VIEWED FROM BOTTOM SIDE" at 5536,-1096.17 h60
  text ".TID" at 2514,-1299.5 h60
  text "TID #:" at 3059.5,-1299.5 h60
  text "TEXAS INSTRUMENTS" at 194.5,-1504.84 h60
  text ".Print_Time" at 1459,-1504.84 h60
  text ".Print_Date" at 2188,-1504.84 h60
  text "GENERATED    :" at 3057.5,-1504.84 h60
  text ".plot_File_Name" at 4730.5,-1504.84 h60
  text "PLOT NAME =" at 5536,-1504.84 h60
M9 Title Sheet:
  drawing of 53 lines, arcs and shapes, not listed
  text "1" at 29.84,7596.5 h70
  text "2" at 2525.5,7596.5 h70
  text "3" at 5014.84,7596.5 h70
  text "4" at 7521.51,7596.5 h70
  text "A" at -1126.5,6453.5 h70
  text "B" at 13673.5,4073.5 h70
  text "PROJECT TITLE:" at 10633.5,-162.5 h45
  text ".PRJ_Title" at 10683.5,-295.83 h70
  text "DESIGNED FOR:" at 10633.5,-463.5 h45
  text ".PRJ_Customer" at 10683.5,-603.5 h70
  text "D" at -1126.5,-671.5 h70
  text "D" at 13673.5,-671.5 h70
  text "FILE NAME:" at 10633.5,-763.5 h45
  text ".PCB_File_Name_No_Path" at 10683.5,-883.5 h70
  text "Texas Instruments (TI) and/or its licensors do not warrant the accuracy or completeness of this specification" at 5664,-1045.34 h45
  text "ENGINEER:" at 10633.5,-1053.5 h45
  text "LAYOUT BY:" at 12138.5,-1053.5 h45
  text "or any information contained therein. TI and/or its licensors do not warrant that this design will meet" at 5619.01,-1158 h45
  text ".PRJ_Engineer" at 10683.5,-1208.49 h70
  text ".PCB_Layout" at 12189,-1208.49 h70
  text "the specifications, will be suitable for your application or fit for any particular purpose, or will operate in" at 5619.01,-1270.67 h45
  text ".Layer_Name" at -133,-1298.49 h60
  text "ALTIUM DESIGNER VERSION:" at 12138.5,-1363.5 h45
  text "an implementation. TI and/or its licensors do not warrant that the design is production worthy. You should" at 5619.01,-1383.33 h45
  text "completely validate and test your design implementation to confirm the system functionality for your application." at 5664,-1496 h45
  text ".print_Scale" at 10683.5,-1496.83 h70
  text ".Application_BuildNumber" at 12189,-1496.83 h70
  text "1" at 29.84,-1703.5 h70
  text "2" at 2525.5,-1703.5 h70
  text "3" at 5014.84,-1703.5 h70
  text "4" at 7521.51,-1703.5 h70
  text "5" at 10020.5,-1703.5 h70
  text "6" at 12525.5,-1703.5 h70
M10 Fab Notes:
  drawing of 152 lines, arcs and shapes, not listed
  text "DESIGN INFORMATION" at 11668.02,5761 h60
  text "MIN. TRACK WIDTH:" at 11023.46,5581 h60
  text "8" at 12119.7,5581 h60
  text "MIL" at 12274.46,5581 h60
  text "MIN. CLEARANCE:" at 11023.46,5449 h60
  text "0.2" at 12059.7,5449 h60
  text "mm" at 12274.46,5449 h60
  text "MIN. VIA PAD SIZE:" at 11023.46,5317 h60
  text "24" at 12089.71,5317 h60
  text "MIL" at 12274.46,5317 h60
  text "0.05mm (2MIL)" at 11718.46,5175.29 h60
  text "MINIMUM ANNULAR RING" at 10694.23,5171 h60
  text "EXTERNAL" at 12426.46,5171 h60
  text "PER" at 10894.23,5053 h60
  text "IPC-D-275 CLASS 2 LEVEL C" at 11114.23,5053 h60
  text "MIL, HOLES" at 12602.46,4940.71 h60
  text "+/-" at 12210,4940 h60
  text "+/-" at 13064,4940 h60
  text "REGISTRATION TOLERANCES:" at 10694.23,4935 h60
  text "METAL" at 11894,4935 h60
  text "5" at 12470.2,4935 h60
  text "3" at 13303.2,4935 h60
  text "MIL" at 13419.46,4935 h60
  text "+/-" at 13064,4822 h60
  text "HOLE SIZE TOLERANCE (UNLESS OTHERWISE SPECIFIED):" at 10694.23,4817 h60
  text "3" at 13303.2,4817 h60
  text "MIL" at 13419.46,4817 h60
  text "MATERIAL:" at 10619.46,4607.54 h60
  text "FR-4 High Tg" at 11605.9,4467.21 h60
  text "FR-408" at 11040.46,4458.64 h60
  text "OTHER" at 12528.46,4458.64 h60
  text "X" at 11451,4455 h60
  text "62 MIL (1.6mm) +/-10%" at 11360.56,4295.92 h60
  text "THICKNESS:" at 10694.23,4291.64 h60
  text "X" at 11232.4,4291.64 h60
  text "OTHER" at 12645.46,4291.64 h60
  text "TOLERANCE:" at 10694.23,4133.64 h60
  text "X" at 11533.53,4133.64 h60
  text "ANSI IPC-6012 TYPE 3 CLASS 2" at 11720.48,4133.64 h60
  text "OTHER +/-" at 11720.46,3977.64 h60
  text "BOW & TWIST:" at 10694.23,3820.64 h60
  text "X" at 11533.53,3820.64 h60
  text "ANSI IPC-6012 TYPE 3 CLASS 2" at 11720.48,3820.64 h60
  text "OTHER +/-" at 11720.46,3662.13 h60
  text "DRILLING:" at 10619.46,3523.64 h60
  text "REFERENCE:" at 10694.23,3406.64 h60
  text "X" at 11342.46,3406.64 h60
  text "AS SHOWN" at 11529.46,3406.64 h60
  text "X" at 12243.46,3406.64 h60
  text "NC_DRILL FILES" at 12380.46,3406.64 h60
  text "PTH COPPER THICKNESS:" at 10694.23,3248.64 h60
  text "X" at 11824.46,3248.64 h60
  text "20-30 um" at 11961.46,3248.64 h60
  text "OTHER" at 12678.46,3248.64 h60
  text "BOARD FINISH:" at 10619.46,3089.64 h60
  text "SILKSCREEN:" at 10774.68,2971.64 h60
  text "X" at 11723.46,2971.64 h60
  text "TOP" at 11849.46,2971.64 h60
  text "X" at 12233.46,2971.64 h60
  text "BOTTOM" at 12360.46,2971.64 h60
  text "SILKSCREEN COLOR:" at 10774.68,2804.64 h60
  text "X" at 11722.42,2804.64 h60
  text "WHITE" at 11849.46,2804.64 h60
  text "OTHER" at 12360.46,2804.64 h60
  text "X" at 11853.42,2645.44 h60
  text "GREEN" at 11980.46,2645.44 h60
  text "OTHER" at 12598.46,2645.44 h60
  text "SOLDER RESIST COLOR:" at 10774.68,2634.64 h60
  text "X" at 11853.42,2475.44 h60
  text "MATTE" at 11980.46,2475.44 h60
  text "SEMI-GLOSS" at 12598,2474.8 h60
  text "IMMERSION GOLD (ENIG)" at 11680.46,2286.92 h60
  text "ENEPIG" at 13018,2283.64 h60
  text "SURFACE FINISH:" at 10619.46,2282.64 h60
  text "X" at 11493.51,2282.64 h60
  text "IMM. TIN/SILVER OR EQUIV" at 10949,2125.64 h60
  text "OTHER" at 12380.46,2125.64 h60
  text "X" at 11490.51,1949.64 h60
  text "ARRAY/PANEL:" at 10619.46,1946.64 h60
  text "CUT AND TRIM PER M1 BOARD OUTLINE" at 11680.46,1942.35 h60
  text "N.C. ROUTE" at 11680.46,1790.64 h60
  text "CERTIFICATION:" at 10619.46,1653.64 h60
  text "MATERIALS AND WORKMANSHIP FOR ALL PCBS" at 11344.46,1653.64 h60
  text "TO MEET OR EXCEED THE REQUIREMENTS OF:" at 11344.46,1555.64 h60
  text "X" at 10970.96,1419.13 h60
  text "ANSI IPC-A-600F CLASS ->" at 11109.96,1419.13 h60
  text "X" at 11785.02,1259.64 h60
  text "RoHS" at 11922.6,1259.96 h60
  text "ALL BOARDS MUST MEET OR EXCEED UL94-V0 REQUIREMENTS." at 10647,1094 h60
  text "PCB MUST BEAR THE UL94V-0 UL REGISTERED MATERIAL ID NUMBER" at 10647,974 h60
  text "ADDITIONAL REQUIREMENTS:" at 10619.46,800.64 h60
  text "MICROSECTION:" at 10694.23,685.64 h60
  text "YES" at 11599.96,685.64 h60
  text "REQUIRED" at 12461.46,529.49 h60
  text "BARE BOARD ELEC. TEST:" at 10694.23,526.64 h60
  text "NONE" at 11999.96,526.64 h60
  text "X" at 12334.46,526.64 h60
  text "PER ORDER" at 13053.46,526.64 h60
  text ".Layer_Name" at -133,-1298.49 h60
M11 Gerber Information:
  lines w10: -1002,-1370.17 5598,-1370.17 ; -1002,-1166.83 5600,-1166.83 ; -1002,-963.5 -1002,-1573.5 3003,-1573.5 5600,-1573.5 5600,-963.5 -1001.5,-963.5 -1001.5,-1573.5 574,-1573.5 ; 1463,-1573.5 1463,-963.5 ; 2730,-1166.83 2730,-963.5 ; 3570,-1166.83 3570,-963.5 ; 4192,-1580 4192,-1377.17
  text "ALL ARTWORK VIEWED FROM TOP SIDE" at -938.5,-1095.67 h60
  text "BOARD #:" at 1538,-1095.67 h60
  text ".PRJ_Number" at 2083.5,-1095.67 h60
  text "REV:" at 2928,-1095.67 h60
  text ".PCB_Rev" at 3219.5,-1095.67 h60
  text "SVN REV:" at 3766,-1095.67 h60
  text ".VersionControl_RevNumber" at 4272,-1095.67 h60
  text "LAYER NAME =" at -938.5,-1298.49 h60
  text "TID #:" at 1538,-1299 h60
  text ".TID" at 2083.5,-1299 h60
  text "PLOT NAME =" at -938.5,-1504.34 h60
  text ".plot_File_Name" at -133,-1504.34 h60
  text "GENERATED    :" at 1540,-1504.34 h60
  text ".Print_Date" at 2409.5,-1504.34 h60
  text ".Print_Time" at 3138.5,-1504.34 h60
  text "TEXAS INSTRUMENTS" at 4403,-1504.34 h60
M12 Stackup:
  drawing of 444 lines, arcs and shapes, not listed
  text "Layer" at 5877.5,7333.2 h60
  text "Name" at 6287.41,7333.2 h60
  text "Material" at 7217.16,7333.2 h60
  text "Thickness" at 8076.93,7333.2 h60
  text "Constant" at 8726.76,7333.2 h60
  text "Board Layer Stack" at 9296.62,7333.2 h60
  text "1" at 5877.5,7213.2 h60
  text "Top Overlay" at 6287.41,7213.2 h60
  text "2" at 5877.5,7093.2 h60
  text "Top Solder" at 6287.41,7093.2 h60
  text "Solder Resist" at 7217.16,7093.2 h60
  text "0.40mil" at 8076.93,7093.2 h60
  text "3.5" at 8726.76,7093.2 h60
  text "3" at 5877.5,6973.2 h60
  text "Top Layer" at 6287.41,6973.2 h60
  text "Copper" at 7217.16,6973.2 h60
  text "1.40mil" at 8076.93,6973.2 h60
  text "4" at 5877.5,6853.2 h60
  text "Dielectric 1" at 6287.41,6853.2 h60
  text "370HR" at 7217.16,6853.2 h60
  text "5.20mil" at 8076.93,6853.2 h60
  text "4.2" at 8726.76,6853.2 h60
  text "5" at 5877.5,6733.2 h60
  text "Layer 2 -GND" at 6287.41,6733.2 h60
  text "Copper" at 7217.16,6733.2 h60
  text "1.42mil" at 8076.93,6733.2 h60
  text "6" at 5877.5,6613.2 h60
  text "Dielectric 2" at 6287.41,6613.2 h60
  text "370HR" at 7217.16,6613.2 h60
  text "43.00mil" at 8076.93,6613.2 h60
  text "4.2" at 8726.76,6613.2 h60
  text "7" at 5877.5,6493.2 h60
  text "Layer 3 - PWR" at 6287.41,6493.2 h60
  text "Copper" at 7217.16,6493.2 h60
  text "1.42mil" at 8076.93,6493.2 h60
  text "8" at 5877.5,6373.2 h60
  text "Dielectric 3" at 6287.41,6373.2 h60
  text "370HR" at 7217.16,6373.2 h60
  text "5.20mil" at 8076.93,6373.2 h60
  text "4.2" at 8726.76,6373.2 h60
  text "9" at 5877.5,6253.2 h60
  text "Bottom Layer" at 6287.41,6253.2 h60
  text "Copper" at 7217.16,6253.2 h60
  text "1.40mil" at 8076.93,6253.2 h60
  text "10" at 5877.5,6133.2 h60
  text "Bottom Solder" at 6287.41,6133.2 h60
  text "Solder Resist" at 7217.16,6133.2 h60
  text "0.40mil" at 8076.93,6133.2 h60
  text "3.5" at 8726.76,6133.2 h60
  text "11" at 5877.5,6013.2 h60
  text "Bottom Overlay" at 6287.41,6013.2 h60
  text ".Layer_Name" at -133,-1298.49 h60
M13 Component Bodies Top:
  text ".Layer_Name" at -133,-1298.49 h60
M14 Component Bodies Bottom:
  text ".Layer_Name" at -133,-1298.49 h60
M15 Courtyards Top:
  text ".Layer_Name" at -133,-1298.49 h60
M16 Courtyards Bottom:
  text ".Layer_Name" at -133,-1298.49 h60
Drill Drawing:
  circle w10: c5903.8,520.41 r27.66
  lines w10: 5876.14,672.52 5931.46,672.52 5903.8,617.21 5876.14,672.52 ; 5876.14,741.67 5876.14,755.5 5889.97,769.33 5876.14,783.15 5876.14,796.98 5889.97,796.98 5903.8,783.15 5917.63,796.98 5931.46,796.98 5931.46,783.15 5917.63,769.33 5931.46,755.5 5931.46,741.67 5917.63,741.67 5903.8,755.5 5889.97,741.67 5876.14,741.67 ; 5876.14,866.13 5931.46,866.13 5931.46,921.44 5876.14,921.44 5876.14,866.13 ; 5876.14,990.59 5931.46,990.59 5931.46,1045.9 5876.14,1045.9 5876.14,990.59 ; 5876.14,1128.87 5889.97,1128.87 5889.97,1115.04 5917.63,1115.04 5917.63,1128.87 5931.46,1128.87 5931.46,1156.53 5917.63,1156.53 5917.63,1170.36 5889.97,1170.36 5889.97,1156.53 5876.14,1156.53 5876.14,1128.87 ; 5876.14,1239.5 5903.8,1253.33 5931.46,1239.5 5917.63,1267.16 5931.46,1294.82 5903.8,1280.99 5876.14,1294.82 5889.97,1267.16 5876.14,1239.5 ; 5876.14,1377.79 5889.97,1377.79 5903.8,1363.96 5917.63,1377.79 5931.46,1377.79 5917.63,1391.62 5931.46,1405.45 5917.63,1405.45 5903.8,1419.28 5889.97,1405.45 5876.14,1405.45 5889.97,1391.62 5876.14,1377.79 ; 5876.14,1516.08 5903.8,1488.42 5931.46,1516.08 5903.8,1543.74 5876.14,1516.08 ; 5887.21,877.19 5920.39,877.19 5920.39,910.38 5887.21,910.38 5887.21,877.19
  lines w12: 5826,455.41 9058.76,455.41 ; 5826,1575.54 9058.76,1575.54 ; 6164.17,330.95 6164.17,1700 ; 6496.28,330.95 6496.28,1700 ; 7133.29,330.95 7133.29,1700 ; 7392.64,330.95 7392.64,1700 ; 7768.06,330.95 7768.06,1700 ; 8491.91,330.95 8491.91,1700 ; 5826,330.95 9058.76,330.95 9058.76,1700 5826,1700 5826,330.95
  text "Symbol" at 5900.68,1612.88 h72
  text "Quantity" at 6201.51,1612.88 h72
  text "Finished Hole Size" at 6533.62,1612.88 h72
  text "Plated" at 7170.62,1612.88 h72
  text "Hole Type" at 7429.98,1612.88 h72
  text "Drill Layer Pair" at 7805.4,1612.88 h72
  text "Hole Tolerance" at 8529.25,1612.88 h72
  text "18" at 6201.51,1488.42 h60
  text "7.87mil (0.200mm)" at 6533.62,1488.42 h60
  text "PTH" at 7170.62,1488.42 h60
  text "Round" at 7429.98,1488.42 h60
  text "Top Layer - Bottom Layer" at 7805.4,1488.42 h60
  text "247" at 6201.51,1363.96 h60
  text "10.00mil (0.254mm)" at 6533.62,1363.96 h60
  text "PTH" at 7170.62,1363.96 h60
  text "Round" at 7429.98,1363.96 h60
  text "Top Layer - Bottom Layer" at 7805.4,1363.96 h60
  text "10" at 6201.51,1239.5 h60
  text "15.00mil (0.381mm)" at 6533.62,1239.5 h60
  text "PTH" at 7170.62,1239.5 h60
  text "Round" at 7429.98,1239.5 h60
  text "Top Layer - Bottom Layer" at 7805.4,1239.5 h60
  text "3" at 6201.51,1115.04 h60
  text "27.56mil (0.700mm)" at 6533.62,1115.04 h60
  text "PTH" at 7170.62,1115.04 h60
  text "Round" at 7429.98,1115.04 h60
  text "Top Layer - Bottom Layer" at 7805.4,1115.04 h60
  text "12" at 6201.51,990.59 h60
  text "28.00mil (0.711mm)" at 6533.62,990.59 h60
  text "PTH" at 7170.62,990.59 h60
  text "Round" at 7429.98,990.59 h60
  text "Top Layer - Bottom Layer" at 7805.4,990.59 h60
  text "4" at 6201.51,866.13 h60
  text "40.00mil (1.016mm)" at 6533.62,866.13 h60
  text "PTH" at 7170.62,866.13 h60
  text "Round" at 7429.98,866.13 h60
  text "Top Layer - Bottom Layer" at 7805.4,866.13 h60
  text "10" at 6201.51,741.67 h60
  text "40.16mil (1.020mm)" at 6533.62,741.67 h60
  text "PTH" at 7170.62,741.67 h60
  text "Round" at 7429.98,741.67 h60
  text "Top Layer - Bottom Layer" at 7805.4,741.67 h60
  text "2" at 6201.51,617.21 h60
  text "59.06mil (1.500mm)" at 6533.62,617.21 h60
  text "PTH" at 7170.62,617.21 h60
  text "Round" at 7429.98,617.21 h60
  text "Top Layer - Bottom Layer" at 7805.4,617.21 h60
  text "8" at 6201.51,492.75 h60
  text "66.93mil (1.700mm)" at 6533.62,492.75 h60
  text "PTH" at 7170.62,492.75 h60
  text "Round" at 7429.98,492.75 h60
  text "Top Layer - Bottom Layer" at 7805.4,492.75 h60
  text "314 Total" at 6201.51,368.29 h60
  text ".Layer_Name" at -133,-1298.49 h60
M17 Embedded Cavity:
  text ".Layer_Name" at -133,-1298.49 h60
M18 Embedded Assembly:
  text ".Layer_Name" at -133,-1298.49 h60
M19 Embedded Keepout:
  text ".Layer_Name" at -133,-1298.49 h60

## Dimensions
-710,-840 to 290,-840 on M2 Board Dimensions
0,0 to 2500,0 on M2 Board Dimensions
0,2300 to 0,0 on M2 Board Dimensions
